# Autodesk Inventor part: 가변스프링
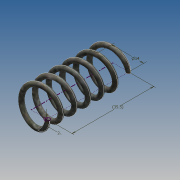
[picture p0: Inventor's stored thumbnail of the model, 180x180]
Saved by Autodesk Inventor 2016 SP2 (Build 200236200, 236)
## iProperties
Created: 2020-02
Part Number: 가변스프링
Material: 강철
Document SubType Name: Modeling
Designer: EZ
Mass: 6.43989 g
Surface Area: 16.6499 cm^2
Volume: 0.820368 cm^3
Density: 7.85 g/cm^3
Appearance: 플레이트
Author: EZ
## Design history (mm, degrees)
sketch "스케치1"
  geometry: L1 (0, 0)-(7, 0); L2 (7, 0)-(7, 35.5); L3 (7, 35.5)-(0, 35.5); L4 (0, 35.5)-(0, 0); C1 r 1 at (7, 0)
  constraints: 8 end point, 2 parallel, 1 centre point, 1 coincident, 1 horizontal, 1 perpendicular
  dimensions: "d0" = 35.5 distance of L1.end L2.end (derived); "d1" = 14 diameter of L2 L4; "d2" = 2 diameter of C1
feature "코일1" pitch "d3" = 10; turns "d5" = 6; dims "d4" = 35.5 (= d0), "d6" = 0, angle "d7" = 90 deg, angle "d8" = 90 deg, "d9" = 0, "d10" = 0
node "작업 평면1"
sketch "스케치2"
  geometry: L1 (1, 0)-(-1, 0) reference; 1 further point
  constraints: 1 horizontal alignment
extrude "돌출1" cut sketch "스케치2" stored distance "d12" = 10; taper "d13" = 0 deg
sketch "스케치3"
  geometry: L1 (-8, 0)-(-6, 0) reference; 1 further point
  constraints: 1 horizontal alignment
extrude "돌출2" cut sketch "스케치3" stored distance "d14" = 10; taper "d15" = 0 deg
node "솔리드1"
node "절단 모서리 투영1"
node "절단 모서리 투영2"
other parameters: "d11" = 90 deg
